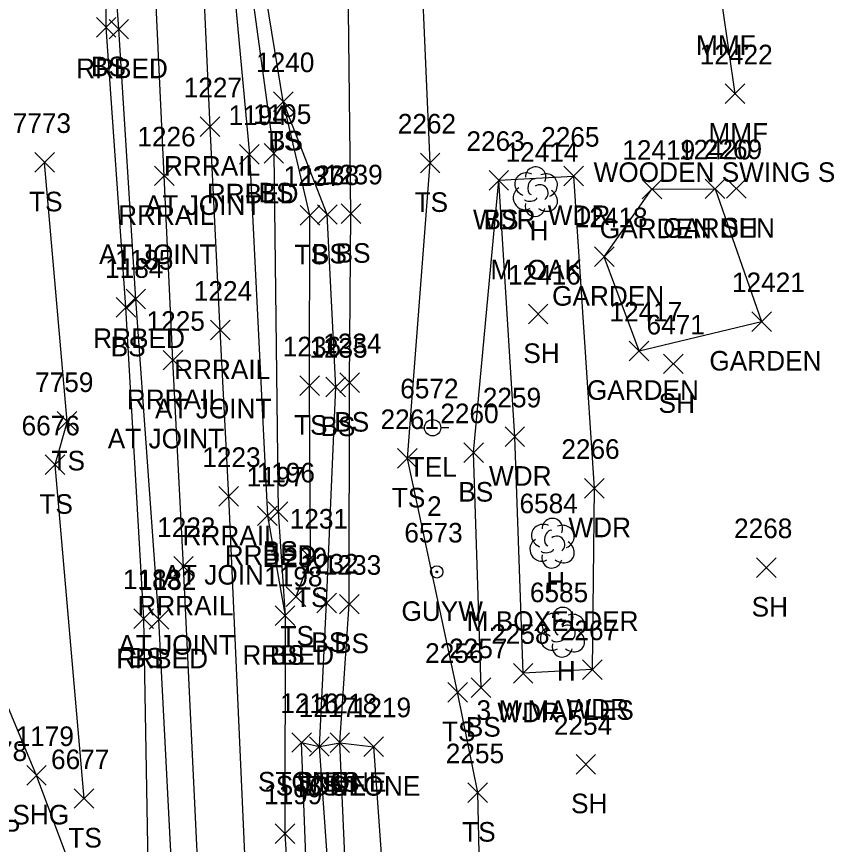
# Model space of a CAD drawing. Extents: x 1769141 to 1770817, y 735471 to 742405.
# Drawn here: x 1770150.6 to 1770233.5, y 740978 to 741062.5 of the extents above; entities that cross this region are included whole.
import ezdxf

# ---------------------------------------------------------------- set-up
doc = ezdxf.new("R2010")
doc.units = 0
for name, color, linetype in [('L_A', 7, 'Continuous'), ('L_C', 7, 'Continuous'), ('L_I', 7, 'Continuous'), ('L_TIC', 7, 'Continuous'), ('LAPB', 7, 'Continuous'), ('LASF', 7, 'Continuous'), ('LAWA', 7, 'Continuous'), ('LDEFAULT', 7, 'Continuous'), ('LELB', 7, 'Continuous'), ('LTD', 7, 'Continuous'), ('P_A', 7, 'Continuous'), ('P_I', 7, 'Continuous'), ('P_TIC', 7, 'Continuous'), ('PSU', 7, 'Continuous'), ('R_A', 7, 'Continuous'), ('R_C', 7, 'Continuous'), ('R_I', 7, 'Continuous'), ('R_TIC', 7, 'Continuous'), ('RR', 7, 'Continuous'), ('RRB', 7, 'Continuous'), ('U_A', 7, 'Continuous'), ('U_C', 7, 'Continuous'), ('U_I', 7, 'Continuous'), ('UP', 7, 'Continuous'), ('UPGW', 7, 'Continuous')]:
    doc.layers.add(name, color=color, linetype=linetype)

msp = doc.modelspace()

# ---------------------------------------------------------------- linework, layer by layer
at = {"layer": 'L_TIC'}
for points in [[(1770158.725, 741060.367), (1770160.725, 741062.367)], [(1770160.725, 741060.367), (1770158.725, 741062.367)], [(1770222.89, 741053.585), (1770224.89, 741055.585)], [(1770224.89, 741053.585), (1770222.89, 741055.585)], [(1770176.798, 741052.788), (1770178.798, 741054.788)], [(1770178.798, 741052.788), (1770176.798, 741054.788)], [(1770176.798, 741052.788), (1770178.798, 741054.788)], [(1770178.798, 741052.788), (1770176.798, 741054.788)], [(1770175.833, 741047.502), (1770177.833, 741049.502)], [(1770177.833, 741047.502), (1770175.833, 741049.502)], [(1770152.444, 741046.586), (1770154.444, 741048.586)], [(1770154.444, 741046.586), (1770152.444, 741048.586)], [(1770191.785, 741046.528), (1770193.785, 741048.528)], [(1770193.785, 741046.528), (1770191.785, 741048.528)], [(1770198.793, 741044.752), (1770200.793, 741046.752)], [(1770200.793, 741044.752), (1770198.793, 741046.752)], [(1770198.793, 741044.752), (1770200.793, 741046.752)], [(1770200.793, 741044.752), (1770198.793, 741046.752)], [(1770206.42, 741045.185), (1770208.42, 741047.185)], [(1770208.42, 741045.185), (1770206.42, 741047.185)], [(1770214.419, 741043.848), (1770216.419, 741045.848)], [(1770216.419, 741043.848), (1770214.419, 741045.848)], [(1770220.853, 741043.885), (1770222.853, 741045.885)], [(1770222.853, 741043.885), (1770220.853, 741045.885)], [(1770223.021, 741043.92), (1770225.021, 741045.92)], [(1770225.021, 741043.92), (1770223.021, 741045.92)], [(1770181.277, 741041.266), (1770183.277, 741043.266)], [(1770183.277, 741041.266), (1770181.277, 741043.266)], [(1770183.692, 741041.338), (1770185.692, 741043.338)], [(1770185.692, 741041.338), (1770183.692, 741043.338)], [(1770179.521, 741041.187), (1770181.521, 741043.187)], [(1770181.521, 741041.187), (1770179.521, 741043.187)], [(1770209.554, 741036.961), (1770211.554, 741038.961)], [(1770211.554, 741036.961), (1770209.554, 741038.961)], [(1770160.742, 741031.797), (1770162.742, 741033.797)], [(1770162.742, 741031.797), (1770160.742, 741033.797)], [(1770202.801, 741031.113), (1770204.801, 741033.113)], [(1770204.801, 741031.113), (1770202.801, 741033.113)], [(1770225.602, 741030.342), (1770227.602, 741032.342)], [(1770227.602, 741030.342), (1770225.602, 741032.342)], [(1770225.602, 741030.342), (1770227.602, 741032.342)], [(1770227.602, 741030.342), (1770225.602, 741032.342)], [(1770213.099, 741027.352), (1770215.099, 741029.352)], [(1770215.099, 741027.352), (1770213.099, 741029.352)], [(1770213.099, 741027.352), (1770215.099, 741029.352)], [(1770215.099, 741027.352), (1770213.099, 741029.352)], [(1770216.6, 741026.026), (1770218.6, 741028.026)], [(1770218.6, 741026.026), (1770216.6, 741028.026)], [(1770179.486, 741023.792), (1770181.486, 741025.792)], [(1770181.486, 741023.792), (1770179.486, 741025.792)], [(1770182.145, 741023.654), (1770184.145, 741025.654)], [(1770184.145, 741023.654), (1770182.145, 741025.654)], [(1770183.56, 741024.112), (1770185.56, 741026.112)], [(1770185.56, 741024.112), (1770183.56, 741026.112)], [(1770154.739, 741020.154), (1770156.739, 741022.154)], [(1770156.739, 741020.154), (1770154.739, 741022.154)], [(1770200.425, 741018.589), (1770202.425, 741020.589)], [(1770202.425, 741018.589), (1770200.425, 741020.589)], [(1770196.211, 741016.971), (1770198.211, 741018.971)], [(1770198.211, 741016.971), (1770196.211, 741018.971)], [(1770189.462, 741016.376), (1770191.462, 741018.376)], [(1770191.462, 741016.376), (1770189.462, 741018.376)], [(1770153.499, 741015.732), (1770155.499, 741017.732)], [(1770155.499, 741015.732), (1770153.499, 741017.732)], [(1770208.529, 741013.335), (1770210.529, 741015.335)], [(1770210.529, 741013.335), (1770208.529, 741015.335)], [(1770176.259, 741010.933), (1770178.259, 741012.933)], [(1770178.259, 741010.933), (1770176.259, 741012.933)], [(1770179.578, 741006.219), (1770181.578, 741008.219)], [(1770181.578, 741006.219), (1770179.578, 741008.219)], [(1770226.095, 741005.245), (1770228.095, 741007.245)], [(1770228.095, 741005.245), (1770226.095, 741007.245)], [(1770178.096, 741002.275), (1770180.096, 741004.275)], [(1770180.096, 741002.275), (1770178.096, 741004.275)], [(1770181.217, 741001.634), (1770183.217, 741003.634)], [(1770183.217, 741001.634), (1770181.217, 741003.634)], [(1770183.534, 741001.508), (1770185.534, 741003.508)], [(1770185.534, 741001.508), (1770183.534, 741003.508)], [(1770162.553, 741000.041), (1770164.553, 741002.041)], [(1770164.553, 741000.041), (1770162.553, 741002.041)], [(1770176.974, 741000.323), (1770178.974, 741002.323)], [(1770178.974, 741000.323), (1770176.974, 741002.323)], [(1770208.324, 740994.834), (1770210.324, 740996.834)], [(1770210.324, 740994.834), (1770208.324, 740996.834)], [(1770201.274, 740994.465), (1770203.274, 740996.465)], [(1770203.274, 740994.465), (1770201.274, 740996.465)], [(1770194.586, 740992.523), (1770196.586, 740994.523)], [(1770196.586, 740992.523), (1770194.586, 740994.523)], [(1770196.981, 740992.991), (1770198.981, 740994.991)], [(1770198.981, 740992.991), (1770196.981, 740994.991)], [(1770178.668, 740987.396), (1770180.668, 740989.396)], [(1770180.668, 740987.396), (1770178.668, 740989.396)], [(1770182.564, 740987.367), (1770184.564, 740989.367)], [(1770184.564, 740987.367), (1770182.564, 740989.367)], [(1770182.564, 740987.367), (1770184.564, 740989.367)], [(1770184.564, 740987.367), (1770182.564, 740989.367)], [(1770180.485, 740986.987), (1770182.485, 740988.987)], [(1770182.485, 740986.987), (1770180.485, 740988.987)], [(1770180.485, 740986.987), (1770182.485, 740988.987)], [(1770182.485, 740986.987), (1770180.485, 740988.987)], [(1770186.024, 740986.971), (1770188.024, 740988.971)], [(1770188.024, 740986.971), (1770186.024, 740988.971)], [(1770186.024, 740986.971), (1770188.024, 740988.971)], [(1770188.024, 740986.971), (1770186.024, 740988.971)], [(1770207.669, 740985.179), (1770209.669, 740987.179)], [(1770209.669, 740985.179), (1770207.669, 740987.179)], [(1770196.639, 740982.28), (1770198.639, 740984.28)], [(1770198.639, 740982.28), (1770196.639, 740984.28)], [(1770156.452, 740981.68), (1770158.452, 740983.68)], [(1770158.452, 740981.68), (1770156.452, 740983.68)]]:
    msp.add_lwpolyline(points, dxfattribs=at)
at = {"layer": 'LAPB'}
for points in [[(1770214.099, 741028.352), (1770210.554, 741037.961), (1770215.419, 741044.848), (1770221.853, 741044.885), (1770226.602, 741031.342)], [(1770214.099, 741028.352), (1770226.602, 741031.342)]]:
    msp.add_lwpolyline(points, dxfattribs=at)
at = {"layer": 'LASF'}
for points in [[(1770187.933, 740904.335), (1770186.25, 740912.517), (1770185.896, 740916.663), (1770184.8, 740920.675), (1770184.076, 740927.626), (1770180.824, 740958.089), (1770179.668, 740988.396), (1770181.485, 740987.987), (1770183.564, 740988.367), (1770187.024, 740987.971)], [(1770187.933, 740904.335), (1770192.494, 740904.26), (1770195.908, 740905.277), (1770194.933, 740916.209), (1770192.16, 740930.231), (1770189.161, 740958.008), (1770187.024, 740987.971)]]:
    msp.add_lwpolyline(points, dxfattribs=at)
at = {"layer": 'LAWA'}
msp.add_lwpolyline([(1770202.274, 740995.465), (1770201.425, 741019.589), (1770199.793, 741045.752), (1770207.42, 741046.185), (1770209.529, 741014.335), (1770209.324, 740995.834), (1770202.274, 740995.465)], dxfattribs=at)
at = {"layer": 'LDEFAULT'}
msp.add_lwpolyline([(1770223.89, 741054.585), (1770222.627, 741063.552)], dxfattribs=at)
at = {"layer": 'LELB'}
for points in [[(1770181.311, 740917.449), (1770179.59, 740921.475), (1770177.118, 740921.478), (1770176.513, 740930.978), (1770171.729, 740930.79), (1770171.373, 740941.995), (1770168.363, 740945.327), (1770165.11, 740957.298), (1770164.098, 740970.155), (1770163.553, 741001.041), (1770161.742, 741032.797), (1770159.725, 741061.367), (1770159.572, 741081.418), (1770161.803, 741087.488), (1770164.515, 741088.618), (1770171.551, 741089.247), (1770172.918, 741077.122), (1770176.833, 741048.502), (1770177.259, 741011.933), (1770177.974, 741001.323)], [(1770191.558, 740906.735), (1770190.424, 740913.16), (1770188.625, 740919.349), (1770188.228, 740928.375), (1770184.924, 740957.584), (1770183.564, 740988.367), (1770184.534, 741002.508), (1770184.56, 741025.112), (1770184.692, 741042.338), (1770184.347, 741072.054), (1770184.959, 741087.855), (1770183.86, 741087.602), (1770172.875, 741083.308)], [(1770202.748, 740852.913), (1770198.081, 740870.23), (1770189.013, 740895.049), (1770187.933, 740904.335), (1770187.578, 740912.346), (1770187.376, 740919.181), (1770186.633, 740920.541), (1770186.963, 740928.353), (1770183.64, 740957.629), (1770181.485, 740987.987), (1770182.217, 741002.634), (1770183.145, 741024.654), (1770182.277, 741042.266), (1770177.798, 741053.788), (1770174.941, 741071.303), (1770172.875, 741083.308)], [(1770246.421, 740860.872), (1770241.286, 740876.805), (1770234.165, 740888.347), (1770224.288, 740902.422), (1770215.42, 740910.628), (1770206.685, 740921.814), (1770206.632, 740941.936), (1770205.486, 740949.715), (1770198.228, 740957.016), (1770197.639, 740983.28), (1770195.586, 740993.523), (1770190.462, 741017.376), (1770192.785, 741047.528), (1770191.915, 741067.839)], [(1770179.096, 741003.275), (1770180.578, 741007.219), (1770180.486, 741024.792), (1770180.521, 741042.187), (1770177.798, 741053.788)], [(1770155.739, 741021.154), (1770153.444, 741047.586)], [(1770197.981, 740993.991), (1770197.211, 741017.971), (1770199.793, 741045.752)], [(1770155.739, 741021.154), (1770154.499, 741016.732)], [(1770154.499, 741016.732), (1770157.452, 740982.68)]]:
    msp.add_lwpolyline(points, dxfattribs=at)
at = {"layer": 'LTD'}
for p, q in [((1770203.498, 741044.641), (1770203.498, 741044.641)), ((1770203.498, 741044.641), (1770203.498, 741044.641)), ((1770205.204, 741008.785), (1770205.204, 741008.785)), ((1770205.204, 741008.785), (1770205.204, 741008.785)), ((1770206.267, 740999.706), (1770206.267, 740999.706)), ((1770206.267, 740999.706), (1770206.267, 740999.706))]:
    msp.add_line(p, q, dxfattribs=at)
for centre in [(1770203.545, 741046.075), (1770205.25, 741010.219), (1770206.314, 741001.14)]:
    msp.add_arc(centre, 1.047, 335.52715, 180.95627, dxfattribs=at)
for centre, major_axis, ratio, start_param, end_param in [((1770202.706, 741045.307), (1.21, -0.512), 0.895232, 1.570796, 4.712389), ((1770203.289, 741045.099), (-0.208, -0.792), 0.645439, 3.141593, 6.283185), ((1770204.539, 741045.224), (-1.141, -0.483), 0.949671, 1.570796, 4.712389), ((1770202.415, 741043.932), (0.584, -1.042), 0.959034, 3.141593, 6.283185), ((1770203.998, 741044.474), (-0.5, 0.667), 0.989748, 3.141593, 6.283185), ((1770204.498, 741043.807), (-1.09, 0.792), 0.841452, 1.570796, 4.712389), ((1770203.498, 741043.141), (0.265, 1.061), 0.942809, 1.570796, 4.712389), ((1770203.04, 741043.891), (-0.625, -0.083), 0.423636, 0, 3.141593), ((1770204.412, 741009.451), (1.21, -0.512), 0.895232, 1.570796, 4.712389), ((1770206.245, 741009.368), (-1.141, -0.483), 0.949671, 1.570796, 4.712389), ((1770204.995, 741009.243), (-0.208, -0.792), 0.645439, 3.141593, 6.283185), ((1770205.704, 741008.618), (-0.5, 0.667), 0.989748, 3.141593, 6.283185), ((1770204.12, 741008.076), (0.584, -1.042), 0.959034, 3.141593, 6.283185), ((1770206.204, 741007.952), (-1.09, 0.792), 0.841452, 1.570796, 4.712389), ((1770204.745, 741008.035), (-0.625, -0.083), 0.423636, 0, 3.141593), ((1770205.204, 741007.285), (0.265, 1.061), 0.942809, 1.570796, 4.712389), ((1770205.475, 741000.372), (1.21, -0.512), 0.895232, 1.570796, 4.712389), ((1770206.058, 741000.164), (-0.208, -0.792), 0.645439, 3.141593, 6.283185), ((1770207.308, 741000.289), (-1.141, -0.483), 0.949671, 1.570796, 4.712389), ((1770206.767, 740999.539), (-0.5, 0.667), 0.989748, 3.141593, 6.283185), ((1770205.184, 740998.997), (0.584, -1.042), 0.959034, 3.141593, 6.283185), ((1770207.267, 740998.872), (-1.09, 0.792), 0.841452, 1.570796, 4.712389), ((1770205.809, 740998.956), (-0.625, -0.083), 0.423636, 0, 3.141593), ((1770206.267, 740998.206), (0.265, 1.061), 0.942809, 1.570796, 4.712389)]:
    msp.add_ellipse(centre, major_axis=major_axis, ratio=ratio, start_param=start_param, end_param=end_param, dxfattribs=at)
at = {"layer": 'P_TIC'}
for points in [[(1770151.614, 740984.038), (1770153.614, 740986.038)], [(1770153.614, 740984.038), (1770151.614, 740986.038)]]:
    msp.add_lwpolyline(points, dxfattribs=at)
at = {"layer": 'PSU'}
for points in [[(1770152.614, 740985.038), (1770143.772, 741006.209)], [(1770170.626, 740937.246), (1770170.65, 740939.505), (1770167.442, 740944.226), (1770163.228, 740956.694), (1770152.614, 740985.038)]]:
    msp.add_lwpolyline(points, dxfattribs=at)
at = {"layer": 'R_TIC'}
for points in [[(1770160.012, 741060.171), (1770162.012, 741062.171)], [(1770162.012, 741060.171), (1770160.012, 741062.171)], [(1770169.329, 741050.221), (1770171.329, 741052.221)], [(1770171.329, 741050.221), (1770169.329, 741052.221)], [(1770173.339, 741047.396), (1770175.339, 741049.396)], [(1770175.339, 741047.396), (1770173.339, 741049.396)], [(1770164.653, 741045.208), (1770166.653, 741047.208)], [(1770166.653, 741045.208), (1770164.653, 741047.208)], [(1770161.752, 741032.641), (1770163.752, 741034.641)], [(1770163.752, 741032.641), (1770161.752, 741034.641)], [(1770170.361, 741029.469), (1770172.361, 741031.469)], [(1770172.361, 741029.469), (1770170.361, 741031.469)], [(1770165.537, 741026.4), (1770167.537, 741028.4)], [(1770167.537, 741026.4), (1770165.537, 741028.4)], [(1770171.224, 741012.506), (1770173.224, 741014.506)], [(1770173.224, 741012.506), (1770171.224, 741014.506)], [(1770175.174, 741010.52), (1770177.174, 741012.52)], [(1770177.174, 741010.52), (1770175.174, 741012.52)], [(1770166.613, 741005.359), (1770168.613, 741007.359)], [(1770168.613, 741005.359), (1770166.613, 741007.359)], [(1770164.111, 740999.961), (1770166.111, 741001.961)], [(1770166.111, 740999.961), (1770164.111, 741001.961)], [(1770176.974, 741000.323), (1770178.974, 741002.323)], [(1770178.974, 741000.323), (1770176.974, 741002.323)], [(1770176.958, 740978.099), (1770178.958, 740980.099)], [(1770178.958, 740978.099), (1770176.958, 740980.099)]]:
    msp.add_lwpolyline(points, dxfattribs=at)
at = {"layer": 'RR'}
for points in [[(1770197.753, 740390.494), (1770195.855, 740429.491), (1770193.917, 740468.481), (1770191.987, 740507.454), (1770190.016, 740546.417), (1770188.175, 740585.45), (1770186.345, 740624.52), (1770184.351, 740663.534), (1770182.414, 740702.58), (1770181.022, 740730.449), (1770179.246, 740766.268), (1770177.157, 740810.299), (1770173.744, 740877.111), (1770171.322, 740927.707), (1770169.445, 740967.981), (1770167.613, 741006.359), (1770166.537, 741027.4), (1770165.653, 741046.208), (1770163.837, 741084.651), (1770161.662, 741123.764), (1770160.41, 741153.194), (1770158.416, 741192.158), (1770156.873, 741228.018)], [(1770203.658, 740370.746), (1770201.768, 740409.672), (1770199.783, 740448.72), (1770197.896, 740487.783), (1770195.957, 740526.733), (1770194.091, 740565.766), (1770192.139, 740604.842), (1770190.284, 740643.849), (1770188.287, 740682.87), (1770186.409, 740721.831), (1770184.146, 740769.997), (1770182.623, 740801.289), (1770179.628, 740862.115), (1770176.856, 740918.905), (1770174.1, 740971.708), (1770172.224, 741013.506), (1770171.361, 741030.469), (1770170.329, 741051.221), (1770168.957, 741081.093), (1770166.986, 741119.982), (1770165.661, 741147.286), (1770164.69, 741163.317), (1770164.281, 741173.164), (1770162.436, 741212.293)]]:
    msp.add_lwpolyline(points, dxfattribs=at)
at = {"layer": 'RRB'}
for points in [[(1770171.551, 741089.247), (1770171.802, 741075.818), (1770174.339, 741048.396), (1770176.174, 741011.52), (1770177.974, 741001.323), (1770177.958, 740979.099), (1770179.842, 740948.528), (1770182.395, 740920.735)], [(1770168.363, 740945.327), (1770167.014, 740957.66), (1770166.65, 740970.662), (1770165.111, 741000.961), (1770162.752, 741033.641), (1770161.012, 741061.171), (1770159.572, 741081.418)]]:
    msp.add_lwpolyline(points, dxfattribs=at)
at = {"layer": 'UP'}
for p, q in [((1770191.373, 741020.505), (1770192.199, 741020.505)), ((1770193.033, 741020.51), (1770193.033, 741020.51)), ((1770194.699, 741020.51), (1770193.866, 741020.51)), ((1770193.866, 741020.51), (1770193.866, 741020.51)), ((1770194.699, 741020.51), (1770194.699, 741020.51))]:
    msp.add_line(p, q, dxfattribs=at)
msp.add_circle((1770193.033, 741020.51), 0.833, dxfattribs=at)
at = {"layer": 'UPGW'}
for radius in [0.625, 0.0833]:
    msp.add_circle((1770193.458, 741005.801), radius, dxfattribs=at)

# ---------------------------------------------------------------- texts
at = {"layer": 'L_A'}
for s, p in [('MMF', (1770219.91, 741058.552)), ('BS', (1770158.166, 741056.367)), ('MMF', (1770221.174, 741049.585)), ('TS', (1770176.207, 741048.788)), ('BS', (1770176.239, 741048.788)), ('BS', (1770175.274, 741043.502)), ('TS', (1770151.854, 741042.586)), ('TS', (1770191.195, 741042.528)), ('WDR', (1770197.155, 741040.752)), ('BS', (1770198.234, 741040.752)), ('WDR', (1770204.782, 741041.185)), ('H', (1770202.931, 741039.641)), ('GARDEN', (1770210.088, 741039.848)), ('GARDEN', (1770216.523, 741039.885)), ('SH', (1770222.51, 741039.92)), ('TS', (1770178.931, 741037.187)), ('BS', (1770180.718, 741037.266)), ('BS', (1770183.133, 741037.338)), ('GARDEN', (1770205.223, 741032.961)), ('BS', (1770160.183, 741027.797)), ('SH', (1770202.289, 741027.113)), ('GARDEN', (1770221.272, 741026.342)), ('GARDEN', (1770221.272, 741026.342)), ('GARDEN', (1770208.768, 741023.352)), ('GARDEN', (1770208.768, 741023.352)), ('SH', (1770216.089, 741022.026)), ('TS', (1770178.896, 741019.792)), ('BS', (1770181.586, 741019.654)), ('BS', (1770183.001, 741020.112)), ('TS', (1770154.149, 741016.154)), ('WDR', (1770198.787, 741014.589)), ('BS', (1770195.652, 741012.971)), ('TS', (1770152.909, 741011.732)), ('TS', (1770188.872, 741012.376)), ('WDR', (1770206.891, 741009.335)), ('BS', (1770175.7, 741006.933)), ('H', (1770204.637, 741003.785)), ('TS', (1770178.988, 741002.219)), ('SH', (1770225.584, 741001.245)), ('TS', (1770177.506, 740998.275)), ('BS', (1770180.658, 740997.634)), ('BS', (1770182.975, 740997.508)), ('BS', (1770161.994, 740996.041)), ('BS', (1770176.415, 740996.323)), ('H', (1770205.7, 740994.706)), ('WDR', (1770206.686, 740990.834)), ('WDR', (1770199.637, 740990.465)), ('BS', (1770196.422, 740988.991)), ('TS', (1770193.996, 740988.523)), ('STONE', (1770175.211, 740983.396)), ('STONE', (1770177.028, 740982.987)), ('STONE', (1770179.108, 740983.367)), ('BS', (1770179.926, 740982.987)), ('BS', (1770182.005, 740983.367)), ('STONE', (1770182.567, 740982.971)), ('STONE', (1770182.567, 740982.971)), ('SH', (1770207.157, 740981.179)), ('TS', (1770196.049, 740978.28)), ('TS', (1770155.862, 740977.68))]:
    msp.add_text(s, height=2, dxfattribs=at).set_placement(p)
at = {"layer": 'L_C'}
for s, p in [('WOODEN SWING SET', (1770209.458, 741045.585)), ('M. OAK', (1770198.931, 741035.641)), ('M.BOXELDER', (1770196.503, 740999.785)), ('3 M.MAPLES', (1770197.511, 740990.706))]:
    msp.add_text(s, height=2, dxfattribs=at).set_placement(p)
at = {"layer": 'L_I'}
for s, p in [('12422', (1770220.3, 741057.585)), ('1240', (1770175.019, 741056.788)), ('1240', (1770175.019, 741056.788)), ('1195', (1770174.707, 741051.502)), ('7773', (1770150.184, 741050.586)), ('2262', (1770189.478, 741050.528)), ('2265', (1770204.113, 741049.185)), ('2263', (1770196.486, 741048.752)), ('2263', (1770196.486, 741048.752)), ('12414', (1770200.475, 741047.641)), ('12419', (1770212.388, 741047.848)), ('12420', (1770218.176, 741047.885)), ('2269', (1770220.707, 741047.92)), ('1237', (1770177.828, 741045.187)), ('1238', (1770179.584, 741045.266)), ('1239', (1770181.991, 741045.338)), ('12418', (1770207.531, 741040.961)), ('1184', (1770159.617, 741035.797)), ('12416', (1770200.722, 741035.113)), ('12421', (1770223.579, 741034.342)), ('12421', (1770223.579, 741034.342)), ('12417', (1770211.075, 741031.352)), ('12417', (1770211.075, 741031.352)), ('6471', (1770214.86, 741030.026)), ('1236', (1770177.738, 741027.792)), ('1234', (1770181.868, 741028.112)), ('1235', (1770180.453, 741027.654)), ('7759', (1770152.472, 741024.154)), ('2259', (1770198.157, 741022.589)), ('2260', (1770193.818, 741020.971)), ('2261', (1770187.722, 741020.376)), ('6676', (1770151.09, 741019.732)), ('2266', (1770206.167, 741017.335)), ('1196', (1770175.078, 741014.933)), ('6584', (1770201.897, 741011.785)), ('1231', (1770178.453, 741010.219)), ('2268', (1770223.788, 741009.245)), ('1230', (1770176.317, 741006.275)), ('1232', (1770179.524, 741005.634)), ('1233', (1770181.841, 741005.508)), ('1198', (1770175.848, 741004.323)), ('1183', (1770161.427, 741004.041)), ('6585', (1770202.96, 741002.706)), ('2258', (1770199.015, 740998.465)), ('2267', (1770206.017, 740998.834)), ('2256', (1770192.271, 740996.523)), ('2257', (1770194.722, 740996.991)), ('1216', (1770177.487, 740991.396)), ('1217', (1770179.359, 740990.987)), ('1217', (1770179.359, 740990.987)), ('1218', (1770181.439, 740991.367)), ('1218', (1770181.439, 740991.367)), ('1219', (1770184.89, 740990.971)), ('1219', (1770184.89, 740990.971)), ('2254', (1770205.409, 740989.179)), ('6677', (1770154.098, 740985.68)), ('2255', (1770194.38, 740986.28))]:
    msp.add_text(s, height=2, dxfattribs=at).set_placement(p)
at = {"layer": 'P_A'}
for s, p in [('SHG', (1770150.15, 740980.038)), ('RDP', (1770145.325, 740978.509))]:
    msp.add_text(s, height=2, dxfattribs=at).set_placement(p)
at = {"layer": 'P_I'}
for s, p in [('1179', (1770150.481, 740988.038)), ('1178', (1770145.711, 740986.509))]:
    msp.add_text(s, height=2, dxfattribs=at).set_placement(p)
at = {"layer": 'R_A'}
for s, p in [('RRBED', (1770156.658, 741056.171)), ('RRRAIL', (1770165.62, 741046.221)), ('RRBED', (1770169.985, 741043.396)), ('RRRAIL', (1770160.944, 741041.208)), ('RRBED', (1770158.398, 741028.641)), ('RRRAIL', (1770166.653, 741025.469)), ('RRRAIL', (1770161.829, 741022.4)), ('RRRAIL', (1770167.516, 741008.506)), ('RRBED', (1770171.82, 741006.52)), ('RRRAIL', (1770162.905, 741001.359)), ('RRBED', (1770160.756, 740995.961)), ('RRBED', (1770173.62, 740996.323))]:
    msp.add_text(s, height=2, dxfattribs=at).set_placement(p)
at = {"layer": 'R_C'}
for p in [(1770163.676, 741042.221), (1770159, 741037.208), (1770164.708, 741021.469), (1770159.884, 741018.4), (1770165.571, 741004.506), (1770160.96, 740997.359)]:
    msp.add_text('AT JOINT', height=2, dxfattribs=at).set_placement(p)
at = {"layer": 'R_I'}
for s, p in [('1227', (1770167.636, 741054.221)), ('1194', (1770172.214, 741051.396)), ('1226', (1770162.905, 741049.208)), ('1185', (1770160.626, 741036.641)), ('1224', (1770168.668, 741033.469)), ('1225', (1770163.845, 741030.4)), ('1223', (1770169.532, 741016.506)), ('1197', (1770174.048, 741014.52)), ('1222', (1770164.92, 741009.359)), ('1198', (1770175.848, 741004.323)), ('1182', (1770162.985, 741003.961)), ('1199', (1770175.824, 740982.099))]:
    msp.add_text(s, height=2, dxfattribs=at).set_placement(p)
at = {"layer": 'U_A'}
for s, p in [('TEL', (1770190.592, 741015.51)), ('GUYW', (1770189.851, 741000.801))]:
    msp.add_text(s, height=2, dxfattribs=at).set_placement(p)
at = {"layer": 'U_C'}
msp.add_text('2', height=2, dxfattribs=at).set_placement((1770192.466, 741011.51))
at = {"layer": 'U_I'}
for s, p in [('6572', (1770189.726, 741023.51)), ('6573', (1770190.151, 741008.801))]:
    msp.add_text(s, height=2, dxfattribs=at).set_placement(p)

doc.saveas('drawing.dxf')
